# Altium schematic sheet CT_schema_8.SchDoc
size 371 x 336 mm
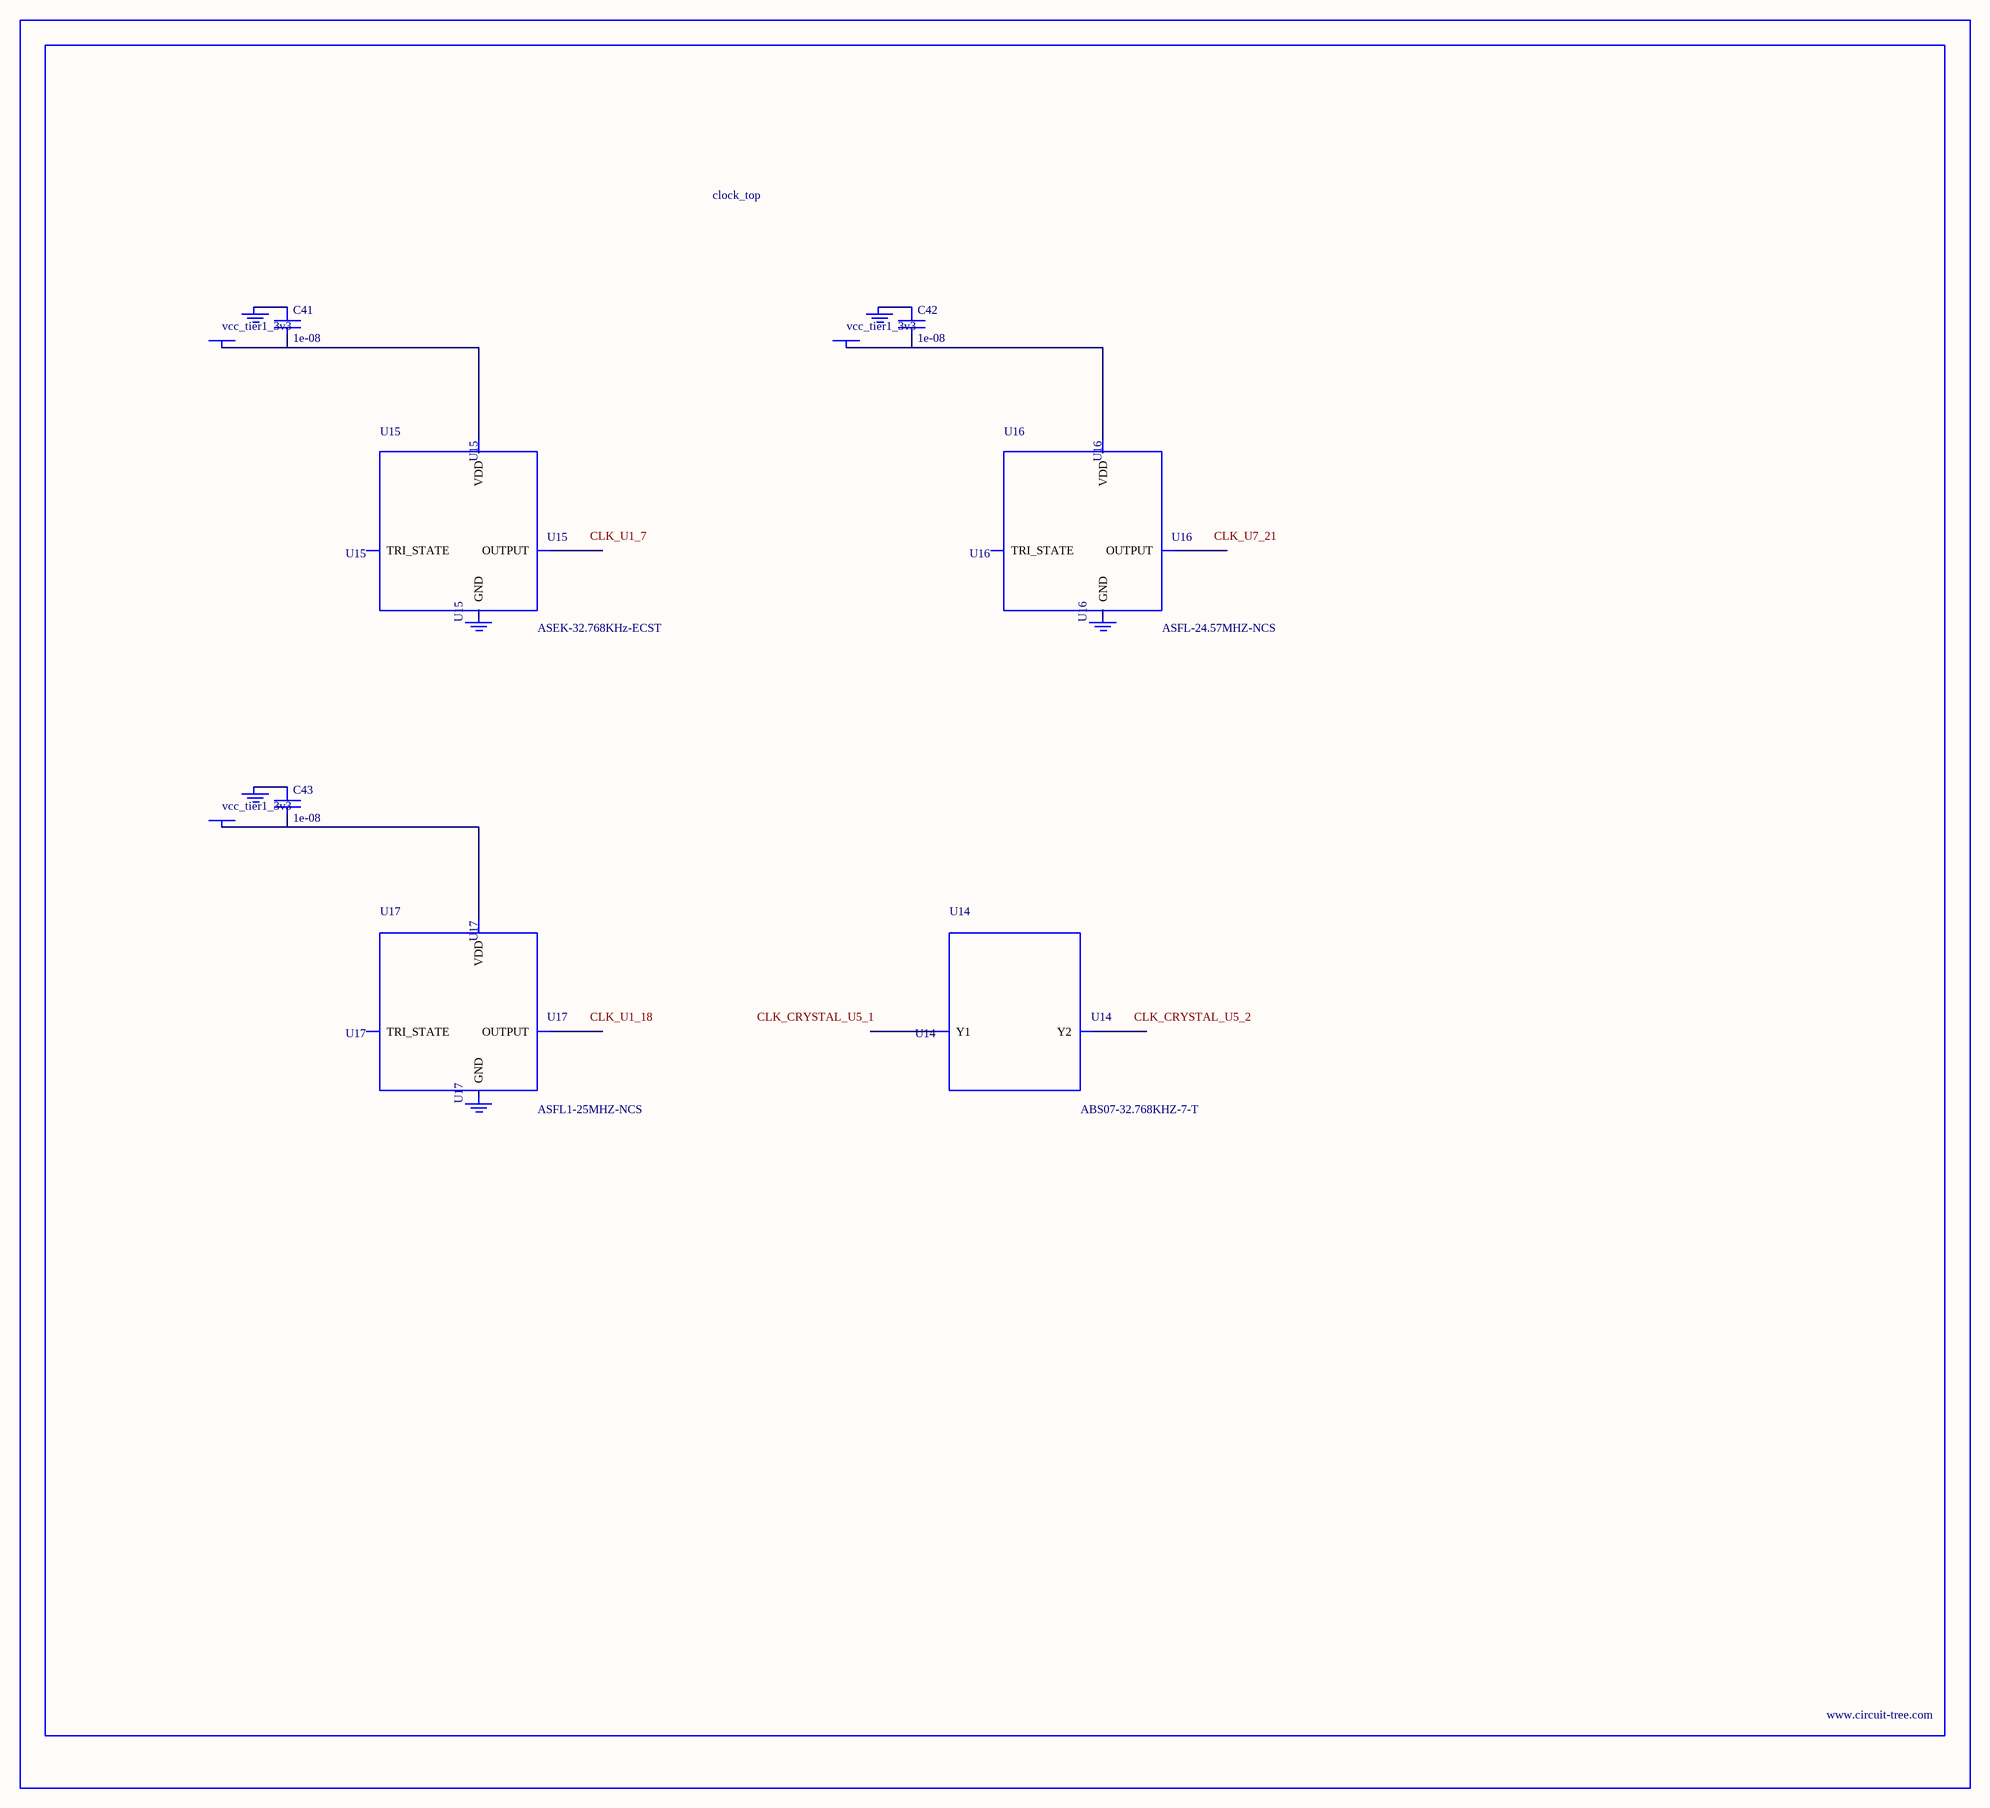
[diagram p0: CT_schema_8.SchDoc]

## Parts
BORDER7  (no value)
C41  1e-08  [C0402]
C42  1e-08  [C0402]
C43  1e-08  [C0402]
GND_INSTANCE_7_0  (no value)
GND_INSTANCE_7_1  (no value)
GND_INSTANCE_7_2  (no value)
GND_INSTANCE_7_3  (no value)
GND_INSTANCE_7_4  (no value)
GND_INSTANCE_7_5  (no value)
POWER_INSTANCE_7_0  vcc_tier1_3v3
POWER_INSTANCE_7_1  vcc_tier1_3v3
POWER_INSTANCE_7_2  vcc_tier1_3v3
U14  ABS07-32.768KHZ-7-T  [ABS07-32.768KHZ-7-T]
U15  ASEK-32.768KHz-ECST  [ASEK]
U16  ASFL-24.57MHZ-NCS  [ASFL1]
U17  ASFL1-25MHZ-NCS  [ASFL1]

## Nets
NetC41_1: C41.1 GND_INSTANCE_7_0.0(GND)
NetC41_2: C41.2 POWER_INSTANCE_7_0.0(PWR) U15.4(VDD)
NetC42_1: C42.1 GND_INSTANCE_7_2.0(GND)
NetC42_2: C42.2 POWER_INSTANCE_7_1.0(PWR) U16.4(VDD)
NetC43_1: C43.1 GND_INSTANCE_7_4.0(GND)
NetC43_2: C43.2 POWER_INSTANCE_7_2.0(PWR) U17.4(VDD)

Not connected (* = marked no-connect by the designer): GND_INSTANCE_7_1 0(GND); GND_INSTANCE_7_3 0(GND); GND_INSTANCE_7_5 0(GND); U14 1(Y1) 2(Y2); U15 1(TRI_STATE) 2(GND) 3(OUTPUT); U16 1(TRI_STATE) 2(GND) 3(OUTPUT); U17 1(TRI_STATE) 2(GND) 3(OUTPUT)

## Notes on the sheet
- Labels drawn without touching a wire or pin: CLK_CRYSTAL_U5_1, CLK_CRYSTAL_U5_2, CLK_U1_7, CLK_U1_18, CLK_U7_21

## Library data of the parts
BORDER7 = BORDER_PAGE7
C41-C43 = C0402C103K3RAC
GND_INSTANCE_7_0-GND_INSTANCE_7_5 = GND
POWER_INSTANCE_7_0-POWER_INSTANCE_7_2 = PWR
